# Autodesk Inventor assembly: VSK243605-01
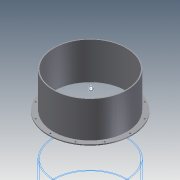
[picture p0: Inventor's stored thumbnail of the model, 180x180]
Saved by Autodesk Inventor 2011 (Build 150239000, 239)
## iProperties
Created: 2010-06
Part Number: VSK243605-01
Document SubType Name: Assembly
Designer: mklassen
OD: 36.000 in
THK: 0.500 in
SKVOFS: 6.000 in
SKLEN: 3.000 ft
Author: mklassen
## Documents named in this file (3)
- O:\cadd\tutorials\inventor 2011\iLogic\VSK243605-01.iam
- O:\cadd\tutorials\inventor 2011\iLogic\Skirt-01-01.ipt
- O:\cadd\tutorials\inventor 2011\iLogic\SkirtFlange-01-01.ipt
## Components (2 placed, 2 different names)
1. Skirt-01:1 — Flush:1, Flush:2, Flush:3
2. SkirtFlange-01:1 — Flush:4, Flush:5
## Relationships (5: Flush 5)
- Flush:1: Skirt-01:1
- Flush:2: Skirt-01:1
- Flush:3: Skirt-01:1
- Flush:4: SkirtFlange-01:1
- Flush:5: SkirtFlange-01:1
